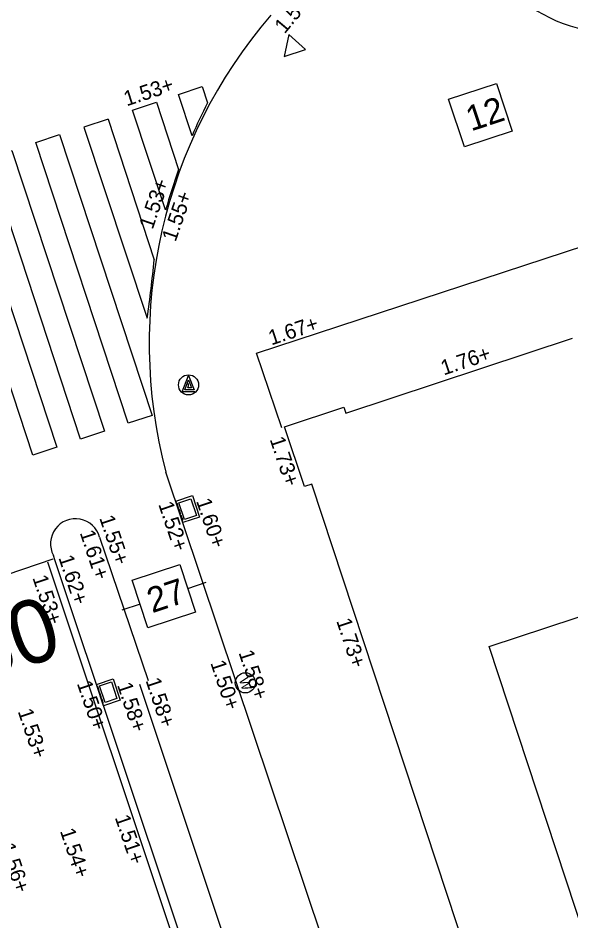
# Model space of a CAD drawing. Extents: x 122462 to 123306, y 485548 to 486417.
# Drawn here: x 122821.1 to 122832.11, y 486155.15 to 486173.11 of the extents above; entities that cross this region are included whole.
import ezdxf

# ---------------------------------------------------------------- set-up
doc = ezdxf.new("R2010")
doc.units = 0
for name, color, linetype in [('B nummers', 7, 'Continuous'), ('B-WE-AL-WERKGRENS-G', 7, 'Continuous'), ('B-WE-GR-BOOM-S', 7, 'Continuous'), ('B-WE-IE-MEUBILAIR_WEGMEUBILAIR-S', 7, 'Continuous'), ('B-WE-OG-HOOGTEPUNT-S', 7, 'Continuous'), ('B-WE-OG-TOPOKAART-G', 7, 'Continuous'), ('B-WE-VH-MATERIAALGRENS-G', 7, 'Continuous'), ('V markering figuratie', 7, 'Continuous'), ('V materiaalscheiding algemeen', 7, 'Continuous'), ('V meubilair trammast', 7, 'Continuous'), ('V meubilair verkeersbord', 7, 'Continuous'), ('V riool trottoirkolk', 7, 'Continuous'), ('V trottoirband 180-200x250 mm specie', 7, 'Continuous')]:
    doc.layers.add(name, color=color, linetype=linetype)

msp = doc.modelspace()

# ---------------------------------------------------------------- linework, layer by layer
at = {"layer": 'B nummers'}
for p, q in [((122824.479, 486161.763), (122824.844, 486161.884)), ((122823.53, 486161.45), (122823.165, 486161.33))]:
    msp.add_line(p, q, dxfattribs=at)
for points in [[(122829.676, 486171.497), (122830.626, 486171.81), (122830.939, 486170.861), (122829.989, 486170.547)], [(122823.373, 486161.925), (122824.323, 486162.238), (122824.636, 486161.289), (122823.686, 486160.975)]]:
    msp.add_lwpolyline(points, close=True, dxfattribs=at)
at = {"layer": 'B-WE-AL-WERKGRENS-G'}
msp.add_lwpolyline([(122857.632, 486078.279), (122830.484, 486160.606), (122900.937, 486183.81), (122887.855, 486222.555), (122665.445, 486149.273), (122678.196, 486110.449), (122807.072, 486152.895), (122835.324, 486068.154)], dxfattribs=at)
at = {"layer": 'B-WE-GR-BOOM-S'}
msp.add_circle((122832.992, 486175.817), 3, dxfattribs=at)
at = {"layer": 'B-WE-IE-MEUBILAIR_WEGMEUBILAIR-S'}
msp.add_circle((122825.627, 486159.884), 0.2, dxfattribs=at)
at = {"layer": 'B-WE-OG-TOPOKAART-G'}
msp.add_lwpolyline([(122835.493, 486145.416), (122834.311, 486145.025), (122834.351, 486144.904), (122833.159, 486144.52), (122832.786, 486145.648), (122832.936, 486145.697), (122826.954, 486163.84), (122826.803, 486163.791), (122826.41, 486164.979), (122827.587, 486165.368), (122827.626, 486165.251), (122832.144, 486166.739)], dxfattribs=at)
at = {"layer": 'B-WE-VH-MATERIAALGRENS-G'}
msp.add_lwpolyline([(122826.354, 486164.961), (122825.848, 486166.443), (122832.41, 486168.591), (122840.754, 486171.332), (122848.12, 486173.75), (122858.853, 486177.307), (122858.545, 486178.241), (122874.617, 486183.538), (122874.928, 486182.584), (122877.008, 486183.297), (122898.435, 486190.341)], dxfattribs=at)
at = {"layer": 'V markering figuratie'}
for points in [[(122824.565, 486170.77), (122824.295, 486171.591), (122824.769, 486171.749), (122824.876, 486171.423)], [(122824.036, 486169.295), (122823.382, 486171.278), (122823.856, 486171.436), (122824.298, 486170.098)], [(122822.898, 486171.098), (122822.41, 486170.939), (122823.673, 486167.142)], [(122822.898, 486171.098), (122823.812, 486168.303)]]:
    msp.add_lwpolyline(points, dxfattribs=at)
for points in [[(122823.294, 486165.048), (122821.452, 486170.635), (122821.927, 486170.793), (122823.769, 486165.206)], [(122822.346, 486164.731), (122820.504, 486170.318), (122820.978, 486170.476), (122822.82, 486164.889)], [(122821.398, 486164.414), (122819.555, 486170.001), (122820.03, 486170.159), (122821.872, 486164.572)]]:
    msp.add_lwpolyline(points, close=True, dxfattribs=at)
for centre, radius, start, end in [((122834.778, 486166.31), 11.144, 152.6873, 156.4088), ((122834.778, 486166.31), 11.144, 160.128, 164.5054), ((122799.43, 486170.633), 24.493, 351.805, 354.5405)]:
    msp.add_arc(centre, radius, start, end, dxfattribs=at)
at = {"layer": 'V materiaalscheiding algemeen'}
for points in [[(122819.003, 486161.406), (122821.801, 486162.349)], [(122829.312, 486139.948), (122829.17, 486139.9), (122821.692, 486162.285)], [(122829.781, 486140.105), (122830.081, 486140.185), (122823.529, 486159.849)]]:
    msp.add_lwpolyline(points, dxfattribs=at)
at = {"layer": 'V meubilair trammast'}
msp.add_lwpolyline([(122826.397, 486172.344), (122826.825, 486172.484), (122826.49, 486172.784)], close=True, dxfattribs=at)
at = {"layer": 'V meubilair verkeersbord'}
msp.add_lwpolyline([(122824.621, 486165.674), (122824.369, 486165.674), (122824.496, 486165.997), (122824.61, 486165.712), (122824.425, 486165.712), (122824.496, 486165.912), (122824.552, 486165.752), (122824.483, 486165.752), (122824.496, 486165.792), (122824.497, 486165.842)], dxfattribs=at)
msp.add_circle((122824.496, 486165.812), 0.2, dxfattribs=at)
at = {"layer": 'V riool trottoirkolk'}
for p, q in [((122824.241, 486163.497), (122824.573, 486163.609)), ((122824.384, 486163.071), (122824.241, 486163.497)), ((122824.573, 486163.609), (122824.716, 486163.182)), ((122824.257, 486163.45), (122824.261, 486163.452)), ((122824.299, 486163.369), (122824.274, 486163.445)), ((122824.288, 486163.355), (122824.293, 486163.357)), ((122824.296, 486163.331), (122824.301, 486163.333)), ((122824.339, 486163.251), (122824.314, 486163.327)), ((122824.328, 486163.237), (122824.333, 486163.238)), ((122824.336, 486163.213), (122824.341, 486163.215)), ((122824.364, 486163.177), (122824.354, 486163.208)), ((122824.379, 486163.132), (122824.364, 486163.177)), ((122824.368, 486163.118), (122824.373, 486163.12)), ((122824.716, 486163.182), (122824.384, 486163.071)), ((122822.66, 486159.854), (122822.992, 486159.965)), ((122822.992, 486159.965), (122823.134, 486159.538)), ((122822.802, 486159.427), (122822.66, 486159.854)), ((122822.676, 486159.807), (122822.68, 486159.808)), ((122822.718, 486159.726), (122822.693, 486159.802)), ((122822.707, 486159.712), (122822.712, 486159.713)), ((122822.715, 486159.688), (122822.72, 486159.69)), ((122822.758, 486159.607), (122822.732, 486159.683)), ((122822.747, 486159.593), (122822.751, 486159.595)), ((122822.755, 486159.569), (122822.759, 486159.571)), ((122822.782, 486159.533), (122822.772, 486159.565)), ((122822.797, 486159.489), (122822.782, 486159.533)), ((122823.134, 486159.538), (122822.802, 486159.427)), ((122822.786, 486159.475), (122822.791, 486159.476))]:
    msp.add_line(p, q, dxfattribs=at)
for points in [[(122824.541, 486163.545), (122824.652, 486163.214), (122824.415, 486163.134), (122824.304, 486163.466)], [(122822.96, 486159.901), (122823.071, 486159.569), (122822.834, 486159.49), (122822.723, 486159.822)]]:
    msp.add_lwpolyline(points, close=True, dxfattribs=at)
for centre, start, end in [((122824.265, 486163.442), 18.5518, 108.5518), ((122824.29, 486163.366), 288.5518, 18.5518), ((122824.304, 486163.324), 18.5518, 108.5518), ((122824.33, 486163.248), 288.5518, 18.5518), ((122824.344, 486163.205), 18.5518, 108.5518), ((122824.37, 486163.129), 288.5518, 18.5518), ((122822.683, 486159.799), 18.4182, 108.4182), ((122822.709, 486159.723), 288.4182, 18.4182), ((122822.723, 486159.68), 18.4182, 108.4182), ((122822.748, 486159.604), 288.4182, 18.4182), ((122822.762, 486159.561), 18.4182, 108.4182), ((122822.788, 486159.486), 288.4182, 18.4182)]:
    msp.add_arc(centre, 0.01, start, end, dxfattribs=at)
at = {"layer": 'V trottoirband 180-200x250 mm specie'}
for points in [[(122834.911, 486138.929), (122832.725, 486138.213), (122824.045, 486164.077)], [(122822.726, 486162.78), (122823.694, 486159.928)], [(122821.835, 486162.331), (122821.806, 486162.417)], [(122829.312, 486139.948), (122821.835, 486162.331)]]:
    msp.add_lwpolyline(points, dxfattribs=at)
for centre, radius, start, end in [((122833.721, 486166.638), 10.009, 139.2783, 194.8273), ((122822.245, 486162.651), 0.498, 15.0523, 208.0126)]:
    msp.add_arc(centre, radius, start, end, dxfattribs=at)

# ---------------------------------------------------------------- texts
at = {"layer": 'B nummers'}
for s, p in [('12', (122830.122, 486170.854)), ('27', (122823.771, 486161.267))]:
    msp.add_text(s, height=0.5, rotation=18.2603, dxfattribs=at).set_placement(p)
at = {"layer": 'B-WE-IE-MEUBILAIR_WEGMEUBILAIR-S'}
msp.add_text('W', height=0.2, rotation=288.2481, dxfattribs=at).set_placement((122825.494, 486159.952))
at = {"layer": 'B-WE-OG-HOOGTEPUNT-S'}
for s, rotation, p in [('1.55+', 50.0725, (122826.409, 486172.785)), ('1.53+', 18.0768, (122823.263, 486171.354)), ('1.53+', 70.7829, (122823.78, 486168.892)), ('1.55+', 70.7829, (122824.237, 486168.645)), ('1.67+', 18.1253, (122826.145, 486166.597)), ('1.76+', 18.3542, (122829.578, 486165.999)), ('1.73+', 288.3809, (122826.109, 486164.731)), ('1.52+', 288.6664, (122823.89, 486163.438)), ('1.60+', 288.6664, (122824.644, 486163.502)), ('1.55+', 288.6664, (122822.716, 486163.165)), ('1.61+', 288.3809, (122822.326, 486162.872)), ('1.62+', 288.3809, (122821.902, 486162.375)), ('1.53+', 288.6664, (122821.383, 486161.976)), ('1.73+', 288.3809, (122827.435, 486161.118)), ('1.58+', 288.3809, (122825.489, 486160.485)), ('1.50+', 288.3809, (122824.927, 486160.282)), ('1.50+', 288.6664, (122822.269, 486159.873)), ('1.58+', 288.3809, (122823.07, 486159.841)), ('1.58+', 288.3809, (122823.637, 486159.933)), ('1.53+', 288.6664, (122821.092, 486159.317)), ('1.51+', 288.6664, (122823.025, 486157.205)), ('1.54+', 288.6664, (122821.932, 486156.937)), ('1.56+', 288.6561, (122820.736, 486156.643))]:
    msp.add_text(s, height=0.3, rotation=rotation, dxfattribs=at).set_placement(p)
at = {"layer": 'V markering figuratie'}
msp.add_text('30', height=1.26, rotation=18.2384, dxfattribs=at).set_placement((122820.258, 486159.867))

doc.saveas('drawing.dxf')
